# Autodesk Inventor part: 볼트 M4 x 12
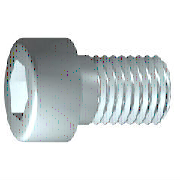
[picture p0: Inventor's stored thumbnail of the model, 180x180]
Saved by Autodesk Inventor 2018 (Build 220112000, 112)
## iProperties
IsCustomPart: 0
Created: 2012-02
Part Number: 볼트 M4 x 12
Material: 강철, 연강
Description: 6각 소켓 머리 캡 나사
Document SubType Name: Modeling
Standard: ISO 4762
Designer: mduedu
Standard Revision: Fourth edition 2004-03-01
Standards Organization: ISO
Language: ko-KR
Size Designation: M4 x 12
Categories: <MemberInstance><Categories><Category DisplayName="조임쇠" InternalName="e4da775c-781d-43d5-af7c-5136215cf5a6" Mnemonic="FSTN"><Category DisplayName="볼트" InternalN
Density: 7.75 g/cm^3
Appearance: 강철
Author: mduedu
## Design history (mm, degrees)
sketch "스케치1"
  geometry: L1 (-1, 0)-(12, 0); L2 (12, 0)-(12, 2); L3 (12, 2)-(1.75, 2); L4 (1.75, 2)-(1.32, 2); L5 (1.32, 2)-(0, 2); L6 (0, 2)-(0, 3.5); L7 (0, 3.5)-(-4, 3.5); L8 (-4, 3.5)-(-4, 1.732); L9 (-4, 1.732)-(-2, 1.732); L10 (-2, 1.732)-(-1, 0); L11 (-7.2, 0)-(15.2, 0) reference; L12 (0, -0.7)-(0, 4.2) reference; L13 (1.75, 2)-(0, 2)
  constraints: 22 end point, 6 parallel, 2 collinear, 2 perpendicular, 1 horizontal, 1 point on line
  dimensions: "d1" = 10.25 distance from line of L3.end L2 (= GEL); "d2" = 0.42952 distance of L4.end L3.end (computed from GAL); "d3" = 4 distance between parallel lines of L8 L6 (= KOH); "d4" = 2 distance of L8.end L9.end (= INTI); "d5" = 60 deg angle of L10 L1; "d6" = 4 diameter of L3 L1 (= GD); "d7" = 4 diameter of L5 L1 (= BDM); "d8" = 3.4641 diameter of L9 L1 (= 1.1547 x SW); "d9" = 7 diameter of L7 L1 (= KOD); "d26" = 12 distance between parallel lines of L12 L2 (= NLG)
revolve "본체" sketch "스케치1" stored, may be unused: angle "d10" = 90 deg
sketch "스케치2"
  geometry: L1 (0, -4.9)-(0, 4.9) reference; L2 (-4.9, 0)-(4.9, 0) reference; L3 (1.732, 0)-(0.866, -1.5); L4 (0.866, -1.5)-(-0.866, -1.5); L5 (-0.866, -1.5)-(-1.732, 0); L6 (-1.732, 0)-(-0.866, 1.5); L7 (-0.866, 1.5)-(0.866, 1.5); L8 (0.866, 1.5)-(1.732, 0); 2 further points
  constraints: 12 end point, 1 coincident, 1 horizontal alignment, 1 point on line, 12 other
extrude "슬롯" join sketch "스케치2" stored distance "d11" = 10; taper "d12" = 0 deg
workplane "Work Plane1"
fillet "Fillet2" dims "d30" = 0.1 (= R)
body "Solid1"
fillet "모깎기1" dims "d17" = 0.4 (= RR)
feature "스레드" dims "d13" = 10.25 (= GEL), "d14" = 0
chamfer "모따기1" distance "d15" = 0.42941 (= -0.5 x SPD + 0.5 x GD); stored, may be unused: second distance "d16" = 0.42941 (= GUL), angle "d27" = 45 deg
other parameters: "GD" = 4 [user parameter; used in 2 equation terms], "NLG" = 12 [user parameter; used in 1 equation term], "GEL" = 10.25 [user parameter; used in 2 equation terms], "KOD" = 7 [user parameter; used in 1 equation term], "KOH" = 4 [user parameter; used in 1 equation term], "INTI" = 2 [user parameter; used in 1 equation term], "GAL" = 0.42941 (= 0.61345 x PTC) [user parameter; used in 1 equation term], "GUL" = 0.42941 (= 0.61345 x PTC) [user parameter; used in 1 equation term], "BDM" = 4 (= NND) [user parameter; used in 1 equation term], "SW" = 3 [user parameter; used in 2 equation terms], "RR" = 0.4 [user parameter; used in 1 equation term], "SPD" = 3.14117 (= NND - 1.2269 x PTC) [user parameter; used in 1 equation term], "d19" = 0, "d28" = 0, "d29" = 0, "R" = 0.1 [user parameter; used in 1 equation term], "TOA" = 30 deg [user parameter], "GD1" = 3.14117 (= THREADDIA - 1.2269 x PTC) [user parameter], "THREADDIA" = 4 [user parameter; used in 1 equation term], "FAWI" = 45 deg [user parameter], "TPU" = 14.28571 (computed from PTC) [user parameter], "PTC" = 0.7 [user parameter; used in 5 equation terms], "NND" = 4 [user parameter; used in 2 equation terms], "E0" = 3.465 (= 1.155 x SW) [user parameter]
